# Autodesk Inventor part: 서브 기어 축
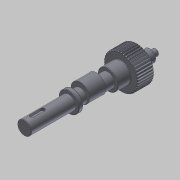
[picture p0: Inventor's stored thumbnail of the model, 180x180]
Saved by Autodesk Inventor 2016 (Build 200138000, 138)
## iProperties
Created: 2018-12
Part Number: 서브 기어 축
Material: 강철, 연강
Document SubType Name: Modeling
Designer: mduedu
Categories: <?xml version="1.0" encoding="UTF-16"?> <MemberInstance><Categories><FamilyTemplate><FamilyTemplateParameter ValueType="xs:double" Id="1" ObjectReferenceKey="da
Density: 7.86 g/cm^3
Appearance: 강철
Mass: 514.759 g
Surface Area: 160.366 cm^2
Volume: 65.491 cm^3
Author: mduedu
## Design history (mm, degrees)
sketch "Sketch1"
  geometry: C1 r 21.3 at (0, 0)
  constraints: 1 centre point
  dimensions: "d0" = 42.6 diameter of C1 (= da_da)
extrude "Extrusion1" new body sketch "Sketch1" distance "d1" = 20 (= da_b); taper "d2" = 0 deg
workplane "Work Plane2"
sketch "Sketch2"
  geometry: C1 r 21.3 at (0, 0) reference; C2 r 20.5 at (0, 0)
  constraints: 1 centre point, 1 coincident
  dimensions: "d3" = 41 diameter of C2 (= da_dw)
feature "피치 지름" sketch "Sketch2" dims "d4" = 10, "d5" = 0
workplane "Work Plane8"
workplane "Work Plane9"
chamfer "모따기1" distance "d49" = 1; stored, may be unused: second distance "d50" = 2, angle "d51" = 45 deg
sketch "스케치3"
  geometry: C1 r 12.5 at (0, 0); 1 further point
  constraints: 1 centre point, 1 coincident
  dimensions: "d52" = 25 diameter of C1
extrude "돌출2" join sketch "스케치3" distance "d53" = 16; taper "d54" = 0 deg
sketch "스케치4"
  geometry: C1 r 8.5 at (0, 0); 1 further point
  constraints: 1 centre point, 1 coincident
  dimensions: "d55" = 17 diameter of C1
extrude "돌출3" join sketch "스케치4" distance "d56" = 103; taper "d57" = 0 deg
sketch "스케치5"
  geometry: C1 r 7.5 at (0, 0); 1 further point
  constraints: 1 centre point, 1 coincident
  dimensions: "d58" = 15 diameter of C1
extrude "돌출4" join sketch "스케치5" distance "d59" = 16; taper "d60" = 0 deg
sketch "스케치6"
  geometry: C1 r 4 at (0, 0); 1 further point
  constraints: 1 centre point, 1 coincident
  dimensions: "d61" = 8 diameter of C1
extrude "돌출5" join sketch "스케치6" distance "d62" = 7; taper "d63" = 0 deg
chamfer "모따기2" distance "d64" = 0.5; stored, may be unused: second distance "d65" = 2, angle "d66" = 45 deg
fillet "모깎기1" dims "d67" = 0.5
feature "스퍼 기어" dims "da_b" = 20, "da_d" = 41, "da_aw" = 31, "da_da" = 42.6, "da_df" = 39.086, "da_dw" = 41, angle "da_beta" = 0 deg, "da_lefttooth" = 0, "da_righttooth" = 0
node "작업 평면11"
sketch "스케치7"
  geometry: C1 r 11.5 at (0, 3); C2 r 8.5 at (0, 0) reference; 1 further point
  constraints: 1 centre point, 1 tangent, 1 vertical alignment
  dimensions: "d69" = 3 distance of point (0, 0) C1.centre; "d70" = 23 diameter of C1 (derived)
extrude "돌출6" join sketch "스케치7" stored distance "d71" = 20; taper "d72" = 0 deg
node "작업 평면12"
sketch "스케치8"
  geometry: C1 r 12.5 at (0, 0) reference; C2 r 12.5 at (0, 0) reference; 1 further point
extrude "돌출7" join sketch "스케치8" distance "d74" = 5; taper "d75" = 0 deg
chamfer "모따기3" distance "d76" = 0.5; stored, may be unused: second distance "d77" = 2, angle "d78" = 45 deg
sketch "스케치9"
  geometry: L1 (-8, 139)-(8, 139) reference; L2 (0, 139)-(0, 0); L3 (-8.5, 84)-(-8.5, 138.5) reference; L4 (-8.5, 115)-(0, 115); L5 (-8.5, 115)-(-8.5, 113.5); L6 (-8.5, 113.5)-(-7, 115); L7 (-7, 115)-(-8.5, 115)
  constraints: 10 end point, 4 point on line, 2 perpendicular, 1 collinear, 1 midpoint
  dimensions: "d79" = 24 distance between parallel lines of L4 L1; "d80" = 3 diameter of L5.end L4; "d81" = 45 deg angle of L6 L3
revolve "회전1" sketch "스케치9" stored, may be unused: angle "d82" = 90 deg
sketch "스케치10"
  geometry: L1 (-8.5, 116.5)-(-7, 115) reference; L2 (-8.5, 113.5)-(-7, 115) reference; 2 further points
  constraints: 1 coincident
node "작업점1"
node "작업 평면13"
sketch "스케치11"
  geometry: L1 (-2.5, 93.5)-(-2.5, 80.5); L2 (2.5, 80.5)-(2.5, 93.5); L3 (-8, 103)-(8, 103) reference; A1 r 2.5 centre (0, 93.5) between (2.5, 93.5) and (-2.5, 93.5); A2 r 2.5 centre (0, 80.5) between (-2.5, 80.5) and (2.5, 80.5); 1 further point
  constraints: 4 end point, 4 point on circle, 4 tangent, 2 centre point, 2 vertical alignment, 1 parallel
  dimensions: "d83" = 7 distance edge to line of A1 L3; "d84" = 18 dimension on A2 A1; "d85" = 5 distance between parallel lines of L1 L2
extrude "돌출8" cut sketch "스케치11" distance "d86" = 3; taper "d87" = 0 deg
sketch "스케치12" dims "d88" = 32
  geometry: C1 r 0.5 at (0, -16); 2 further points
  constraints: 2 vertical alignment, 1 centre point, 1 coincident, 2 other
  dimensions: "d89" = 1 diameter of C1
extrude "돌출9" join sketch "스케치12" distance "d90" = 0.3; taper "d91" = 0 deg
sketch "스케치13"
  geometry: C1 r 11.5 at (0, 3) reference; 1 further point
  node "절단 모서리 투영1"
body "Solid1"
body "Srf1"
node "투영된 루프1"
other parameters: "d16" = 31 (= da_aw), "d17" = 0, "d34" = 0.76624 (computed from da_z), "d39" = 0, "d41" = 0, "d43" = 31 (= da_aw), "d46" = 31 (= da_aw), "d47" = 0, "d48" = 0, "d68" = 24, "d73" = 48
